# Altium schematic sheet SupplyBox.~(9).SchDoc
size B; SheetNumber: 1; SheetTotal: 1
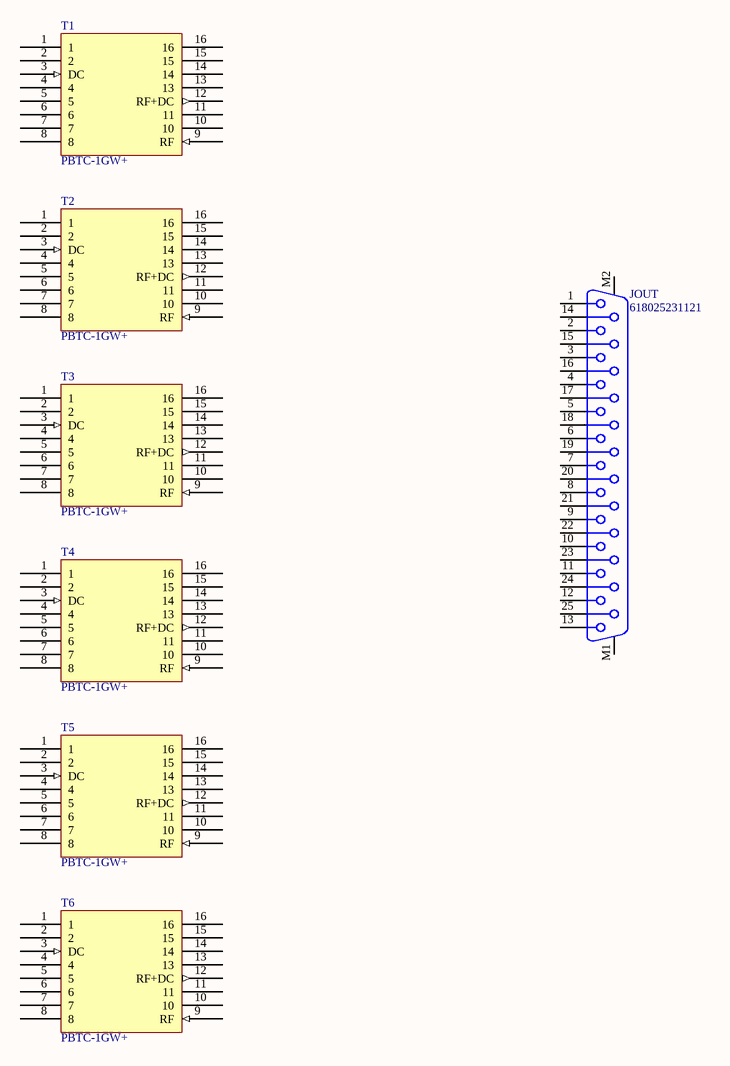
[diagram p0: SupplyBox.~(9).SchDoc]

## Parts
JOUT  618025231121  [618025231121]
T1  PBTC-1GW+  [PBTC-1GW+]
T2  PBTC-1GW+  [PBTC-1GW+]
T3  PBTC-1GW+  [PBTC-1GW+]
T4  PBTC-1GW+  [PBTC-1GW+]
T5  PBTC-1GW+  [PBTC-1GW+]
T6  PBTC-1GW+  [PBTC-1GW+]

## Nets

Not connected (* = marked no-connect by the designer): JOUT 1 2 3 4 5 6 7 8 9 10 11 12 13 14 15 16 17 18 19 20 21 22 23 24 25 M1 M2; T1 1 2 3(DC) 4 5 6 7 8 9(RF) 10 11 12(RF+DC) 13 14 15 16; T2 1 2 3(DC) 4 5 6 7 8 9(RF) 10 11 12(RF+DC) 13 14 15 16; T3 1 2 3(DC) 4 5 6 7 8 9(RF) 10 11 12(RF+DC) 13 14 15 16; T4 1 2 3(DC) 4 5 6 7 8 9(RF) 10 11 12(RF+DC) 13 14 15 16; T5 1 2 3(DC) 4 5 6 7 8 9(RF) 10 11 12(RF+DC) 13 14 15 16; T6 1 2 3(DC) 4 5 6 7 8 9(RF) 10 11 12(RF+DC) 13 14 15 16

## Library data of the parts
JOUT = CMP-1502-00202-2: NexarPartId: 18818207; Pitch: 2.77mm; Operating Supply Voltage: 125V; Gender: Female; Insulation Resistance: 5GΩ; Contact Resistance: 30mΩ; Current Rating: 3A; Number of Contacts: 25
T1-T6 = CMP-00025-00003-1: Monitor TEE DC Block, 0.1MHz Min, 1000MHz Max, 1dB Insertion Loss-Max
